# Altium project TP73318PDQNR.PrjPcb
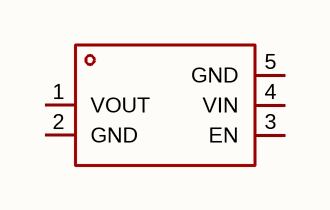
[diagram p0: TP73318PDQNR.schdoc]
1 sheet, 1 parts. Net scope: global (net labels, ports and power ports of the same name join across sheets).

## Sheet TP73318PDQNR.schdoc
size 127 x 101 mm

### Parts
U?  tp73318pdqnr  [XDFN-4_L1.0-W1.0-P0.65-BL-EP]  (value not drawn)

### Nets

Not connected (* = marked no-connect by the designer): U? 1(VOUT) 2(GND) 3(EN) 4(VIN) 5(GND)

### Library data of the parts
U? = tp73318pdqnr: 输出极性:正极;工作电压:5.5V;输出电压:1.8V;输出电流:300mA;电源纹波抑制比(PSRR):70dB@(1kHz);输出类型:固定;; Manufacturer: TECH PUBLIC(台舟); AddInBom: yes; ModelId: 0095c5b582f64c2fb25ce9a94c122b3a; ModelName: XDFN-4_L1.0-W1.0-H0.6-P0.65-BL-EP; ModelTransform: 39.37,40.1574,0,0,0,0,0.005,-0.005,0; Output Configuration: 正极; Voltage - Supply: 5.5V; Output Voltage: 1.8V; Output Current: 300mA; Voltage Dropout: 470mV@(300mA); standby current: 15uA; Noise: 48uVrms; Output Type: 固定; Number of Outputs: 1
